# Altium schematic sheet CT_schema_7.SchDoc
size 371 x 245 mm
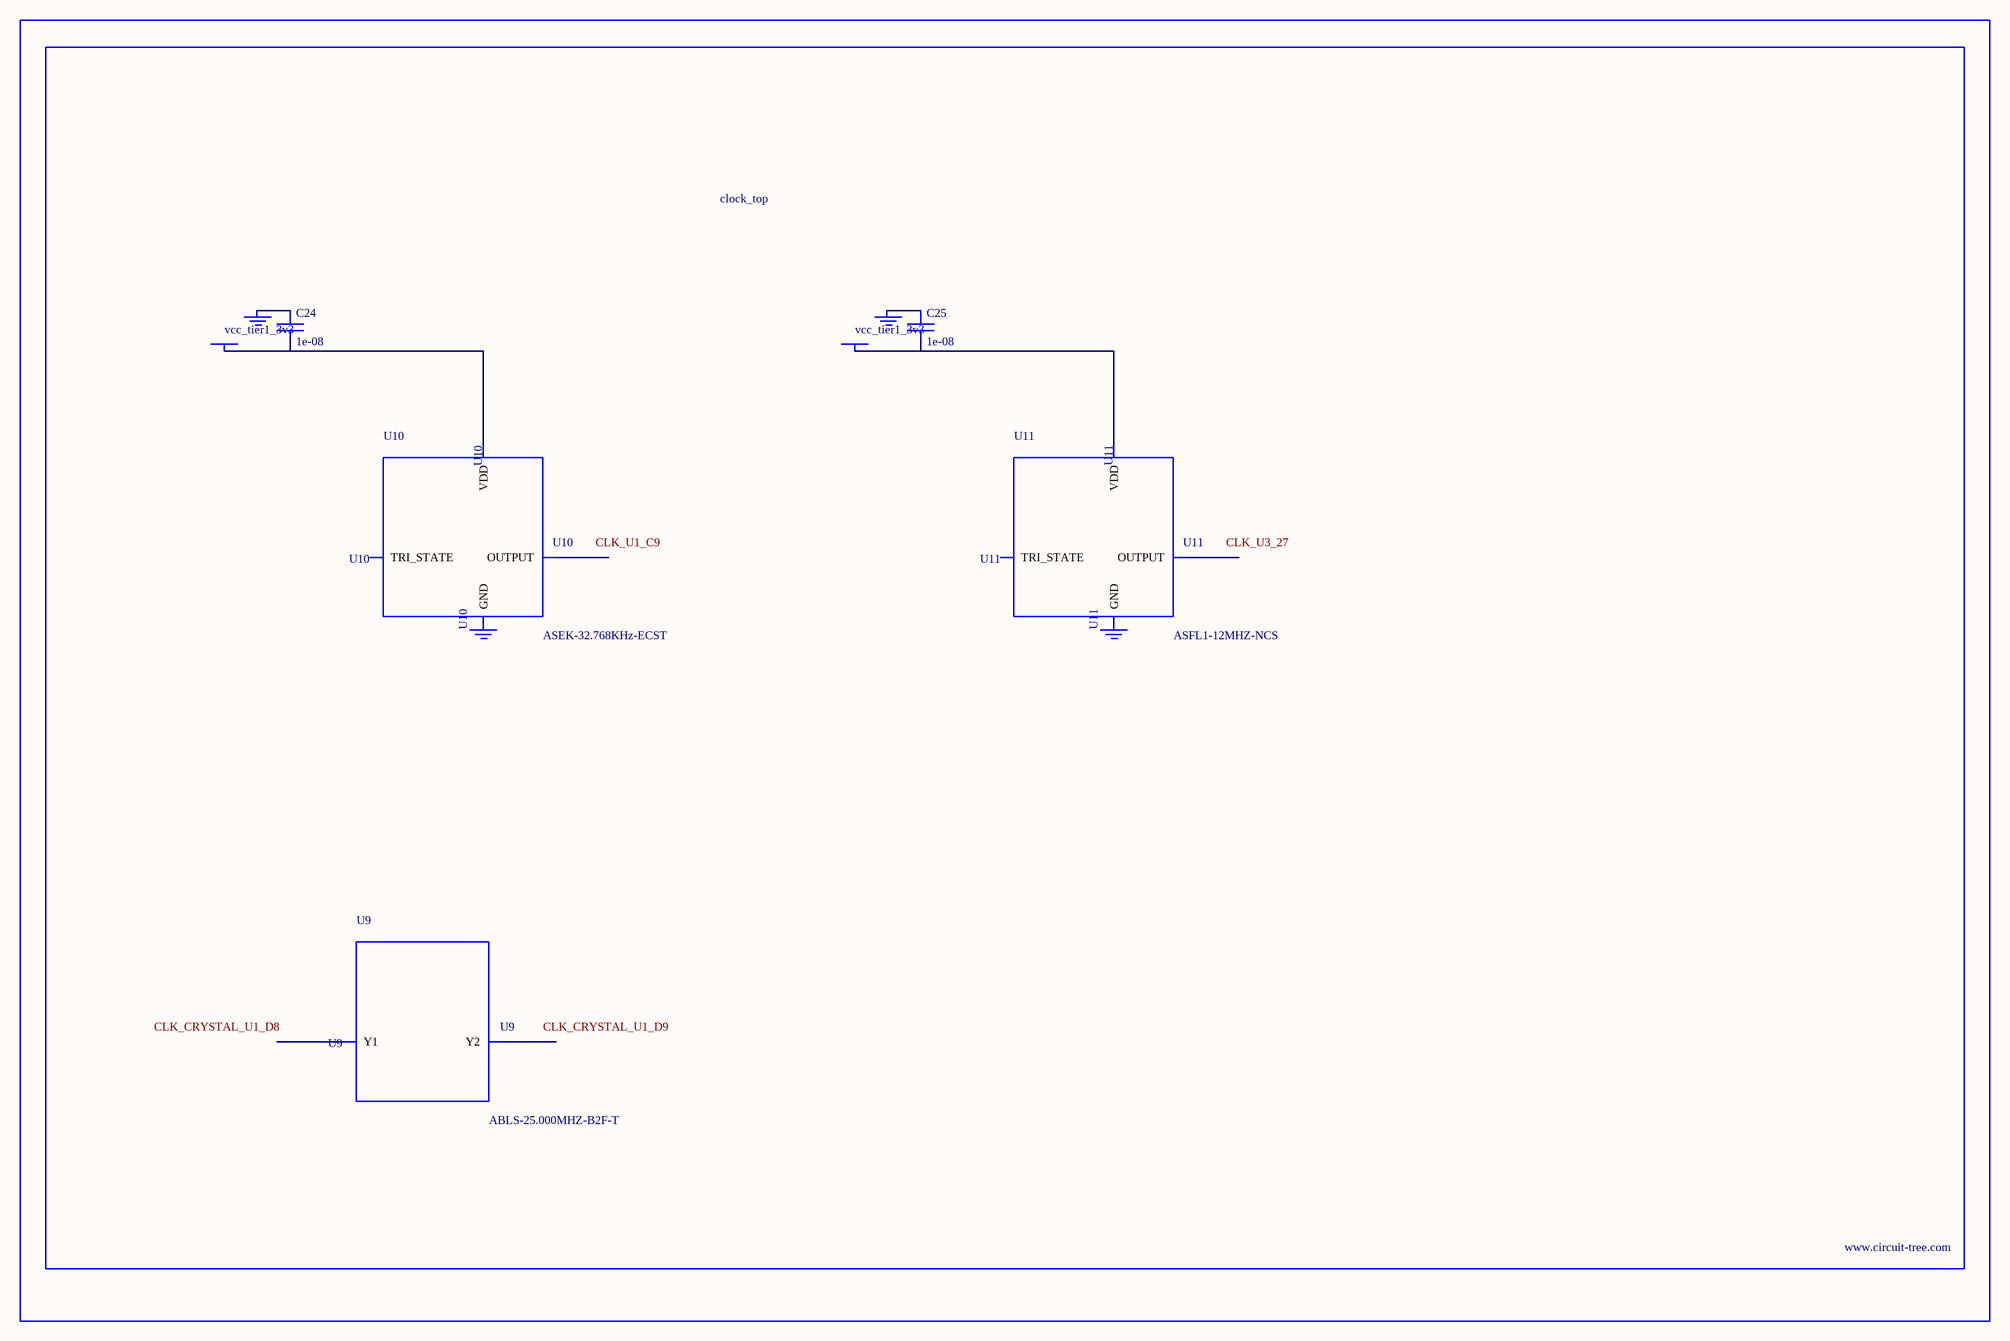
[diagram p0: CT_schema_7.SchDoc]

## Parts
BORDER6  (no value)
C24  1e-08  [C0402]
C25  1e-08  [C0402]
GND_INSTANCE_6_0  (no value)
GND_INSTANCE_6_1  (no value)
GND_INSTANCE_6_2  (no value)
GND_INSTANCE_6_3  (no value)
POWER_INSTANCE_6_0  vcc_tier1_3v3
POWER_INSTANCE_6_1  vcc_tier1_3v3
U9  ABLS-25.000MHZ-B2F-T  [ABLS-25.000MHZ-B2F-T]
U10  ASEK-32.768KHz-ECST  [ASEK]
U11  ASFL1-12MHZ-NCS  [ASFL1]

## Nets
NetC24_1: C24.1 GND_INSTANCE_6_0.0(GND)
NetC24_2: C24.2 POWER_INSTANCE_6_0.0(PWR) U10.4(VDD)
NetC25_1: C25.1 GND_INSTANCE_6_2.0(GND)
NetC25_2: C25.2 POWER_INSTANCE_6_1.0(PWR) U11.4(VDD)

Not connected (* = marked no-connect by the designer): GND_INSTANCE_6_1 0(GND); GND_INSTANCE_6_3 0(GND); U9 1(Y1) 2(Y2); U10 1(TRI_STATE) 2(GND) 3(OUTPUT); U11 1(TRI_STATE) 2(GND) 3(OUTPUT)

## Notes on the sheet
- Labels drawn without touching a wire or pin: CLK_CRYSTAL_U1_D8, CLK_CRYSTAL_U1_D9, CLK_U1_C9, CLK_U3_27

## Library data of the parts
BORDER6 = BORDER_PAGE6
C24 C25 = C0402C103K3RAC
GND_INSTANCE_6_0-GND_INSTANCE_6_3 = GND
POWER_INSTANCE_6_0 POWER_INSTANCE_6_1 = PWR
